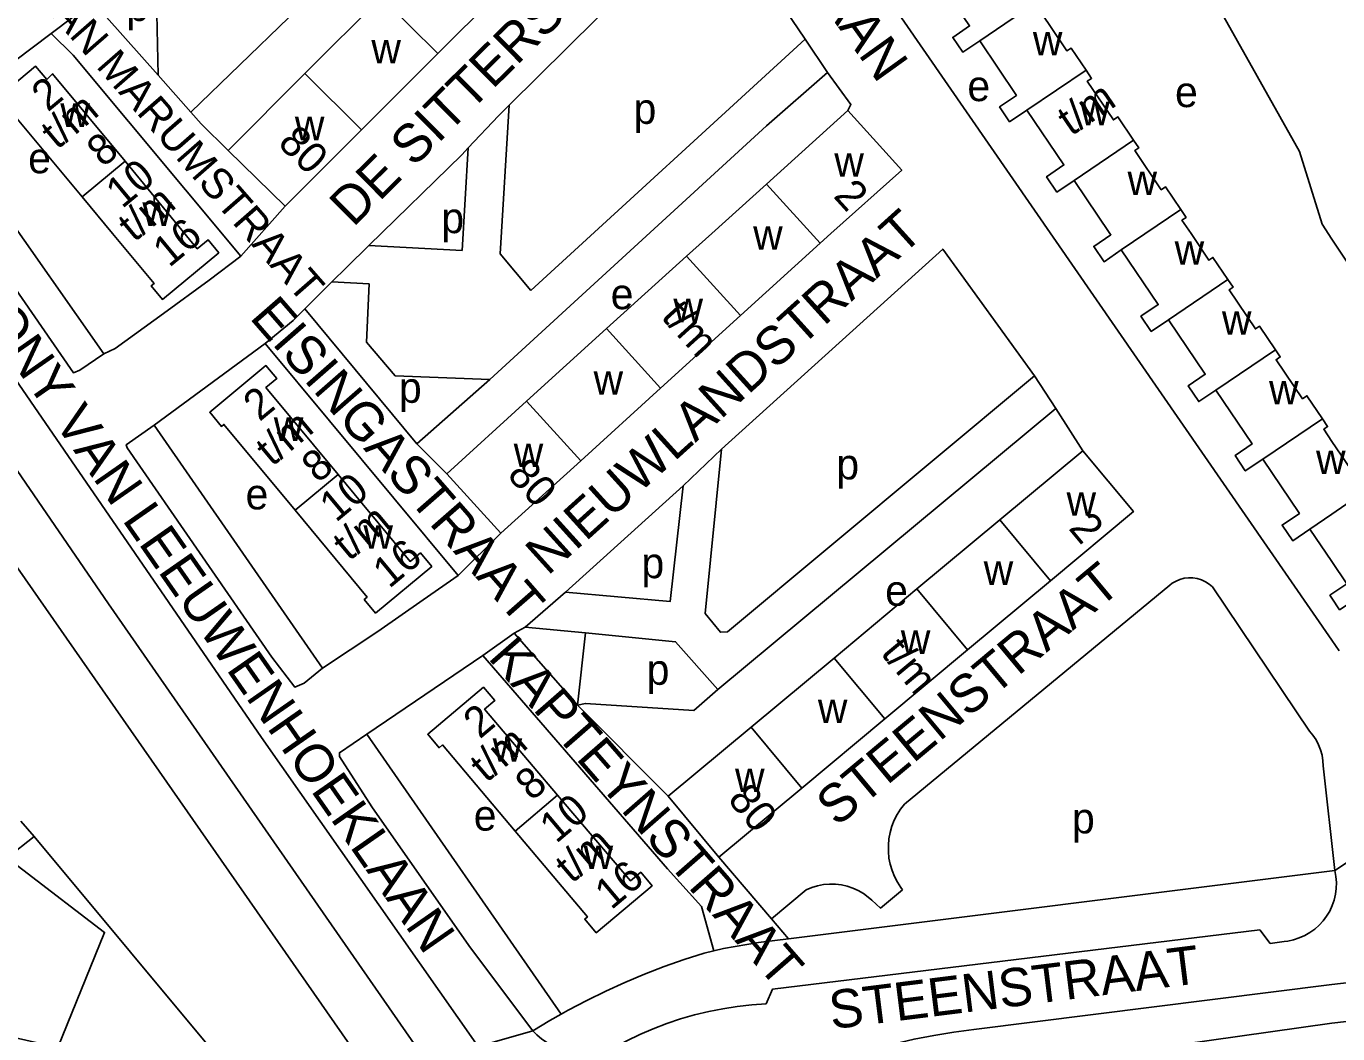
# Model space of a CAD drawing. Extents: x 159902 to 161769, y 383692 to 384875.
# Drawn here: x 160329.3 to 160500.8, y 384145.4 to 384277.1 of the extents above; entities that cross this region are included whole.
import ezdxf

# ---------------------------------------------------------------- set-up
doc = ezdxf.new("R2010")
doc.units = 0
for name, color, linetype in [('BLT_Basislijn', 7, 'Continuous'), ('BLT_Bebouwing', 7, 'Continuous'), ('BLT_Centroide', 7, 'Continuous'), ('BLT_Huisnummer_reeks', 7, 'Continuous'), ('BLT_Onderverdeling_panden', 7, 'Continuous'), ('BLT_Straatnaam', 7, 'Continuous'), ('BLT_Straatnaam_verkleind', 7, 'Continuous'), ('BLT_Vlakafsluiter', 7, 'Continuous')]:
    doc.layers.add(name, color=color, linetype=linetype)

msp = doc.modelspace()

# ---------------------------------------------------------------- linework, layer by layer
at = {"layer": 'BLT_Basislijn'}
for p, q in [((160337.69, 384280.72), (160346.57, 384270.7)), ((160340.11, 384201.6), (160288.34, 384276.94)), ((160347.99, 384201.77), (160297.57, 384275.01)), ((160332.58, 384276.15), (160317.87, 384265.05)), ((160395.28, 384242.55), (160431.13, 384275.39)), ((160431.13, 384275.39), (160434.06, 384271.04)), ((160346.57, 384270.7), (160350.87, 384265.85)), ((160392.46, 384266.78), (160391.29, 384247.35)), ((160317.87, 384265.05), (160339.47, 384234.3)), ((160350.87, 384265.85), (160352.22, 384264.33)), ((160391.07, 384265.4), (160387.12, 384261.18)), ((160352.22, 384264.33), (160355.75, 384260.84)), ((160387.12, 384261.18), (160386.28, 384260.28)), ((160387.12, 384261.18), (160386.3, 384247.76)), ((160374.12, 384248.43), (160386.28, 384260.28)), ((160357.37, 384247.06), (160363.19, 384253.56)), ((160371.24, 384245.61), (160374.12, 384248.43)), ((160374.12, 384248.43), (160386.3, 384247.76)), ((160391.29, 384247.35), (160395.28, 384242.55)), ((160371.24, 384245.61), (160369.3, 384243.69)), ((160369.3, 384243.69), (160365.74, 384240.14)), ((160369.3, 384243.69), (160374.18, 384243.42)), ((160365.74, 384240.14), (160364.24, 384238.65)), ((160365.74, 384240.14), (160380.38, 384222.53)), ((160360.58, 384235.63), (160364.24, 384238.65)), ((160346.07, 384224.95), (160360.58, 384235.63)), ((160360.58, 384235.63), (160385.81, 384205.33)), ((160461.11, 384231.42), (160463.92, 384227.15)), ((160419.74, 384190.41), (160463.92, 384227.15)), ((160467.42, 384221.62), (160463.92, 384227.15)), ((160346.07, 384224.95), (160368.07, 384193.18)), ((160380.38, 384222.53), (160384.31, 384218.61)), ((160415.21, 384217.03), (160420.23, 384221.83)), ((160399.82, 384203.14), (160415.21, 384217.03)), ((160325.46, 384210.23), (160383.08, 384127.6)), ((160385.81, 384205.33), (160391.37, 384210.83)), ((160394.54, 384198.54), (160399.82, 384203.14)), ((160478.82, 384204.05), (160444.15, 384175.44)), ((160484.38, 384203.81), (160497.05, 384184.98)), ((160384.44, 384137.82), (160340.11, 384201.6)), ((160393.13, 384197.76), (160389, 384194.87)), ((160394.54, 384198.54), (160393.13, 384197.76)), ((160401.38, 384188.38), (160393.13, 384197.76)), ((160394.54, 384198.54), (160402.45, 384197.8)), ((160401.38, 384188.38), (160402.45, 384197.8)), ((160373.86, 384184.59), (160389, 384194.87)), ((160413.16, 384166.98), (160389, 384194.87)), ((160401.38, 384188.38), (160413.26, 384176.46)), ((160373.86, 384184.59), (160399.27, 384147.98)), ((160498.85, 384180.42), (160500.37, 384166.74)), ((160328.65, 384173.22), (160330.39, 384171.22)), ((160419.88, 384168.51), (160426.74, 384160.44)), ((160428.96, 384157.83), (160500.37, 384166.74)), ((160431.3, 384164.25), (160426.74, 384160.44)), ((160426.74, 384160.44), (160428.96, 384157.83)), ((160387.2, 384156.98), (160393.43, 384148.64)), ((160425.03, 384157.34), (160428.96, 384157.83)), ((160419.21, 384156.26), (160417.95, 384155.97)), ((160395.57, 384145.81), (160393.43, 384148.64))]:
    msp.add_line(p, q, dxfattribs=at)
for points in [[(160437.92, 384298.9), (160433.19, 384295.39), (160432.67, 384294.41), (160432.8, 384294.03), (160500, 384196.88), (160500.95, 384195.48)], [(160474.04, 384299.43), (160495.78, 384260.7), (160498.73, 384251.22), (160500, 384249.27), (160516.04, 384225.27), (160524.9, 384211.57)], [(160392.46, 384266.78), (160419.14, 384293.17), (160431.13, 384275.39)], [(160341.22, 384284.55), (160346.29, 384284.78), (160346.57, 384270.7)], [(160371.44, 384283.91), (160363.52, 384283.56), (160363.67, 384278.22), (160350.87, 384265.85)], [(160336.71, 384279.66), (160335.43, 384278.29), (160332.58, 384276.15)], [(160332.58, 384276.15), (160335.47, 384273.29), (160357.37, 384247.06)], [(160389.95, 384230.91), (160426.08, 384264.06), (160434.06, 384271.04)], [(160436.74, 384266.06), (160437.13, 384266.84), (160434.06, 384271.04)], [(160391.07, 384265.4), (160392.46, 384266.78)], [(160317.87, 384265.05), (160315.2, 384263.24), (160314.49, 384262.19), (160335.53, 384231.79), (160336.36, 384232.14), (160339.47, 384234.3)], [(160420.23, 384221.83), (160449.14, 384247.96), (160461.11, 384231.42)], [(160339.47, 384234.3), (160340.98, 384234.97), (160347.26, 384239.54), (160353.25, 384243.92), (160357.37, 384247.06)], [(160374.18, 384243.42), (160373.8, 384235.82), (160377.55, 384231.42), (160389.95, 384230.91)], [(160380.38, 384222.53), (160389.95, 384230.91)], [(160420.23, 384221.83), (160418.09, 384200.36), (160420.08, 384197.9), (160421, 384197.93), (160461.11, 384231.42)], [(160346.07, 384224.95), (160342.38, 384222.38), (160342.55, 384222.01), (160361.42, 384194.64), (160364.45, 384190.7), (160365.65, 384191.22), (160368.07, 384193.18)], [(160415.21, 384217.03), (160413.52, 384201.92), (160399.82, 384203.14)], [(160368.07, 384193.18), (160375.28, 384198.01), (160381.23, 384202.12), (160385.81, 384205.33)], [(160484.38, 384203.81), (160483.95, 384204.18), (160483.47, 384204.5), (160482.95, 384204.74), (160482.4, 384204.91), (160481.84, 384205), (160481.27, 384205.02), (160480.7, 384204.95), (160480.14, 384204.8), (160479.62, 384204.58), (160479.12, 384204.29), (160478.82, 384204.05)], [(160388.43, 384143.74), (160360.11, 384184.15), (160347.99, 384201.77)], [(160419.74, 384190.41), (160414.21, 384196.65), (160402.45, 384197.8)], [(160419.74, 384190.41), (160416.6, 384187.69), (160402.43, 384188.6), (160401.38, 384188.38)], [(160373.86, 384184.59), (160370.27, 384182.15), (160370.3, 384181.66), (160374.53, 384175.09), (160387.2, 384156.98)], [(160497.05, 384184.98), (160497.52, 384184.43), (160497.93, 384183.83), (160498.26, 384183.19), (160498.52, 384182.52), (160498.71, 384181.82), (160498.82, 384181.1), (160498.85, 384180.42)], [(160444.15, 384175.44), (160443.63, 384174.78), (160443.18, 384174.07), (160442.8, 384173.32), (160442.49, 384172.54), (160442.25, 384171.73), (160442.1, 384170.91), (160442.02, 384170.07), (160442.02, 384169.23), (160442.1, 384168.39), (160442.27, 384167.57), (160442.51, 384166.76), (160442.82, 384165.98), (160443.21, 384165.23), (160443.66, 384164.53), (160443.87, 384164.25)], [(160276.65, 384143.51), (160311.94, 384100.91), (160323.37, 384087.49), (160323.99, 384087.44), (160338.85, 384099.46), (160367.31, 384123.31), (160368.68, 384124.84), (160368.13, 384125.84), (160330.39, 384171.22)], [(160330.39, 384171.22), (160326.86, 384168.4), (160328.88, 384166.85)], [(160413.16, 384166.98), (160417.6, 384162.05), (160419.21, 384156.26)], [(160313.28, 384152.52), (160317.83, 384147.19), (160333.48, 384143.65), (160339.59, 384158.66), (160328.88, 384166.85)], [(160500.37, 384166.74), (160500.51, 384165.97), (160500.58, 384165.2), (160500.56, 384164.43), (160500.46, 384163.66), (160500.29, 384162.9), (160500.04, 384162.17), (160499.71, 384161.46), (160499.31, 384160.8), (160498.85, 384160.17), (160498.33, 384159.6), (160497.75, 384159.09), (160497.12, 384158.64), (160496.44, 384158.25), (160495.73, 384157.94), (160494.99, 384157.7), (160494.23, 384157.54), (160493.74, 384157.48)], [(160431.3, 384164.25), (160432.02, 384164.55), (160432.77, 384164.77), (160433.54, 384164.92), (160434.32, 384164.98), (160435.1, 384164.97), (160435.88, 384164.88), (160436.64, 384164.71), (160437.38, 384164.46), (160438.09, 384164.14), (160438.77, 384163.74), (160439.4, 384163.28), (160439.87, 384162.87)], [(160439.87, 384162.87), (160440.99, 384161.84), (160443.87, 384164.25)], [(160493.74, 384157.48), (160491.94, 384157.2), (160490.56, 384159), (160426.88, 384151.26), (160426.05, 384149.32)], [(160425.03, 384157.34), (160420.47, 384156.55), (160419.21, 384156.26)], [(160417.95, 384155.97), (160415.32, 384155.13), (160412.72, 384154.21), (160410.15, 384153.21), (160407.6, 384152.14), (160405.09, 384151), (160402.61, 384149.78), (160400.17, 384148.49), (160399.27, 384147.98)], [(160527.99, 384155.07), (160500, 384151.86), (160453.18, 384146)], [(160426.05, 384149.32), (160424.16, 384149.19), (160422.27, 384148.99), (160420.4, 384148.7), (160418.54, 384148.33), (160416.7, 384147.88), (160414.87, 384147.36), (160413.07, 384146.76), (160411.3, 384146.09), (160409.56, 384145.34), (160407.85, 384144.52), (160406.18, 384143.63), (160405.74, 384143.38)], [(160513.4, 384148.33), (160500, 384146.79), (160468.24, 384142.34), (160453.61, 384138.94), (160446.91, 384136.68), (160439.69, 384133.26), (160431.46, 384128.18), (160423.21, 384121.53)], [(160399.27, 384147.98), (160397.77, 384147.14), (160395.57, 384145.81)], [(160405.74, 384143.38), (160404.92, 384143.11), (160404.08, 384142.92), (160403.22, 384142.81), (160402.36, 384142.78), (160401.5, 384142.83), (160400.64, 384142.95), (160399.8, 384143.16), (160398.99, 384143.44), (160398.2, 384143.8), (160397.45, 384144.23), (160396.74, 384144.72), (160396.09, 384145.28), (160395.57, 384145.81)], [(160453.18, 384146), (160450.58, 384145.65), (160447.98, 384145.22), (160445.39, 384144.72), (160442.83, 384144.13), (160440.28, 384143.47), (160437.75, 384142.73), (160435.24, 384141.91), (160432.77, 384141.02), (160430.32, 384140.05), (160427.9, 384139.01), (160425.51, 384137.9), (160423.16, 384136.71), (160420.85, 384135.46), (160418.57, 384134.13), (160416.34, 384132.74), (160414.94, 384131.8)]]:
    msp.add_lwpolyline(points, dxfattribs=at)
at = {"layer": 'BLT_Bebouwing'}
for p, q in [((160393.08, 384283.49), (160383.12, 384273.51)), ((160365.77, 384270.9), (160375.73, 384280.89)), ((160383.12, 384273.51), (160373.15, 384263.54)), ((160355.75, 384260.84), (160365.77, 384270.9)), ((160426.11, 384256.47), (160436.74, 384266.06)), ((160373.15, 384263.54), (160363.19, 384253.56)), ((160363.19, 384253.56), (160355.75, 384260.84)), ((160433.12, 384248.75), (160422.69, 384239.27)), ((160405.18, 384237.57), (160415.62, 384247.05)), ((160422.69, 384239.27), (160412.25, 384229.79)), ((160394.74, 384228.09), (160405.18, 384237.57)), ((160412.25, 384229.79), (160401.81, 384220.31)), ((160384.31, 384218.61), (160394.74, 384228.09)), ((160401.81, 384220.31), (160391.37, 384210.83)), ((160456.58, 384212.58), (160467.42, 384221.62)), ((160391.37, 384210.83), (160384.31, 384218.61)), ((160445.75, 384203.55), (160456.58, 384212.58)), ((160463.2, 384204.63), (160452.37, 384195.6)), ((160434.92, 384194.52), (160445.75, 384203.55)), ((160424.09, 384185.49), (160434.92, 384194.52)), ((160452.37, 384195.6), (160441.54, 384186.57)), ((160441.54, 384186.57), (160430.71, 384177.54)), ((160413.26, 384176.46), (160424.09, 384185.49)), ((160430.71, 384177.54), (160419.88, 384168.51)), ((160419.88, 384168.51), (160413.26, 384176.46))]:
    msp.add_line(p, q, dxfattribs=at)
for points in [[(160447.79, 384284.29), (160452.63, 384277.12), (160450.43, 384275.63), (160451.76, 384273.68), (160453.96, 384275.17)], [(160461.74, 384280.43), (160462.42, 384279.43), (160461.86, 384279.05), (160465.36, 384273.86), (160465.91, 384274.24), (160467.86, 384271.35)], [(160453.96, 384275.17), (160458.77, 384268.05), (160456.55, 384266.55), (160457.87, 384264.6), (160460.12, 384266.12)], [(160336.63, 384254.79), (160327.27, 384266.03), (160326.87, 384265.7), (160325.33, 384267.51), (160330.56, 384271.85), (160332.04, 384270.12), (160332.77, 384270.87), (160342.25, 384259.46)], [(160467.86, 384271.35), (160468.58, 384270.28), (160468.02, 384269.9), (160471.44, 384264.84), (160472.02, 384265.23), (160474.08, 384262.19)], [(160436.74, 384266.06), (160443.77, 384258.3), (160434.5, 384250), (160433.12, 384248.75)], [(160460.12, 384266.12), (160464.96, 384258.96), (160462.7, 384257.43), (160464.06, 384255.42), (160466.3, 384256.93)], [(160474.08, 384262.19), (160474.75, 384261.19), (160474.23, 384260.84), (160477.69, 384255.71), (160478.25, 384256.09), (160480.26, 384253.12)], [(160342.25, 384259.46), (160351.7, 384248.02), (160353.11, 384249.18), (160354.51, 384247.49), (160347.15, 384241.4), (160345.68, 384243.17), (160346.04, 384243.46), (160340.62, 384250), (160336.63, 384254.79)], [(160415.62, 384247.05), (160418.94, 384250), (160426.11, 384256.47)], [(160466.3, 384256.93), (160470.99, 384250), (160471.11, 384249.83), (160468.87, 384248.31), (160470.22, 384246.32), (160472.47, 384247.85)], [(160480.26, 384253.12), (160480.94, 384252.11), (160480.4, 384251.74), (160481.58, 384250.01), (160483.91, 384246.51), (160484.44, 384246.87), (160486.39, 384243.98)], [(160472.47, 384247.85), (160477.29, 384240.72), (160475.03, 384239.19), (160476.38, 384237.2), (160478.63, 384238.73)], [(160486.39, 384243.98), (160487.07, 384242.98), (160486.56, 384242.63), (160490, 384237.54), (160490.53, 384237.9), (160492.62, 384234.81)], [(160478.63, 384238.73), (160483.45, 384231.6), (160481.2, 384230.09), (160482.6, 384228.03), (160484.82, 384229.53)], [(160492.62, 384234.81), (160493.25, 384233.87), (160492.71, 384233.51), (160496.16, 384228.41), (160496.72, 384228.79), (160498.75, 384225.79)], [(160364.48, 384213.84), (160355.17, 384225.05), (160354.85, 384224.79), (160353.32, 384226.64), (160360.67, 384232.74), (160362.08, 384231.04), (160360.66, 384229.86), (160370.09, 384218.5)], [(160484.82, 384229.53), (160489.57, 384222.5), (160487.33, 384220.98), (160488.68, 384218.98), (160490.95, 384220.51)], [(160498.75, 384225.79), (160499.44, 384224.77), (160498.93, 384224.42), (160500, 384222.84), (160502.42, 384219.25), (160502.95, 384219.61), (160504.91, 384216.71)], [(160467.42, 384221.62), (160474.05, 384213.67), (160463.2, 384204.63)], [(160490.95, 384220.51), (160495.74, 384213.43), (160493.49, 384211.91), (160494.88, 384209.86), (160497.12, 384211.37)], [(160370.09, 384218.5), (160379.52, 384207.15), (160380.87, 384208.26), (160382.34, 384206.49), (160375, 384200.4), (160373.52, 384202.17), (160373.9, 384202.49), (160364.48, 384213.84)], [(160497.12, 384211.37), (160499.99, 384207.12), (160501.96, 384204.23), (160500, 384202.91), (160499.74, 384202.73), (160500, 384202.35), (160501, 384200.84), (160503.25, 384202.3)], [(160393.24, 384171.9), (160383.74, 384183.18), (160383.29, 384182.8), (160381.81, 384184.56), (160389.1, 384190.7), (160390.57, 384188.96), (160389.25, 384187.84), (160398.79, 384176.62)], [(160398.79, 384176.62), (160408.33, 384165.4), (160409.67, 384166.53), (160411.15, 384164.77), (160403.85, 384158.62), (160402.34, 384160.41), (160402.68, 384160.7), (160393.24, 384171.9)]]:
    msp.add_lwpolyline(points, dxfattribs=at)
at = {"layer": 'BLT_Onderverdeling_panden'}
for p, q in [((160375.73, 384280.89), (160383.12, 384273.51)), ((160453.96, 384275.17), (160461.74, 384280.43)), ((160365.77, 384270.9), (160373.15, 384263.54)), ((160460.12, 384266.12), (160467.86, 384271.35)), ((160466.3, 384256.93), (160474.08, 384262.19)), ((160342.25, 384259.46), (160336.63, 384254.79)), ((160426.11, 384256.47), (160433.12, 384248.75)), ((160472.47, 384247.85), (160480.26, 384253.12)), ((160415.62, 384247.05), (160422.69, 384239.27)), ((160478.63, 384238.73), (160486.39, 384243.98)), ((160405.18, 384237.57), (160412.25, 384229.79)), ((160484.82, 384229.53), (160492.62, 384234.81)), ((160394.74, 384228.09), (160401.81, 384220.31)), ((160490.95, 384220.51), (160498.75, 384225.79)), ((160370.09, 384218.5), (160364.48, 384213.84)), ((160456.58, 384212.58), (160463.2, 384204.63)), ((160445.75, 384203.55), (160452.37, 384195.6)), ((160434.92, 384194.52), (160441.54, 384186.57)), ((160424.09, 384185.49), (160430.71, 384177.54)), ((160398.79, 384176.62), (160393.24, 384171.9))]:
    msp.add_line(p, q, dxfattribs=at)
msp.add_lwpolyline([(160497.12, 384211.37), (160500, 384213.32), (160504.91, 384216.71)], dxfattribs=at)
at = {"layer": 'BLT_Vlakafsluiter'}
for p, q in [((160500.37, 384166.74), (160510.3, 384173.37)), ((160388.43, 384143.74), (160395.57, 384145.81))]:
    msp.add_line(p, q, dxfattribs=at)

# ---------------------------------------------------------------- texts
at = {"layer": 'BLT_Centroide'}
for s, p in [('p', (160342.42, 384277.78)), ('w', (160374.45, 384272.22)), ('w', (160460.91, 384273.27)), ('e', (160452.35, 384267.3)), ('e', (160479.49, 384266.52)), ('w', (160333.8, 384263.92)), ('p', (160408.72, 384264.33)), ('w', (160467.09, 384264.16)), ('w', (160364.45, 384262.19)), ('e', (160329.59, 384257.87)), ('w', (160434.96, 384257.41)), ('w', (160473.28, 384255.03)), ('w', (160344.52, 384251)), ('p', (160383.59, 384250.05)), ('w', (160424.35, 384247.88)), ('w', (160479.44, 384245.92)), ('e', (160405.73, 384240.11)), ('w', (160413.93, 384238.41)), ('w', (160485.62, 384236.77)), ('w', (160403.49, 384228.94)), ('p', (160378.05, 384227.88)), ('w', (160491.78, 384227.66)), ('w', (160361.7, 384222.89)), ('w', (160393.05, 384219.47)), ('p', (160435.22, 384217.87)), ('w', (160497.92, 384218.56)), ('e', (160358.01, 384213.95)), ('w', (160465.31, 384213.12)), ('w', (160373.41, 384208.8)), ('p', (160409.75, 384204.96)), ('w', (160454.48, 384204.09)), ('e', (160441.61, 384201.35)), ('w', (160443.65, 384195.06)), ('p', (160410.43, 384191.03)), ('w', (160432.81, 384186.03)), ('w', (160390.3, 384180.98)), ('w', (160421.98, 384177)), ('e', (160387.83, 384171.97)), ('p', (160466.02, 384171.61)), ('w', (160402.19, 384166.95))]:
    msp.add_text(s, height=4, dxfattribs=at).set_placement(p)
at = {"layer": 'BLT_Huisnummer_reeks'}
for s, rotation, p in [('2', 39.7075, (160332.16, 384265.8)), ('t/m', 34.073, (160465.9, 384262.66)), ('t/m', 39.697, (160333.38, 384260.87)), ('8', 39.697, (160339.38, 384258.55)), ('80', 315.6184, (160362.08, 384261.64)), ('10', 39.697, (160341.87, 384253.16)), ('2', 312.2513, (160434.72, 384254.83)), ('t/m', 39.697, (160343.45, 384248.77)), ('16', 39.7102, (160348.02, 384245.46)), ('t/m', 312.255, (160412.19, 384239.05)), ('2', 39.7075, (160359.83, 384225.34)), ('t/m', 39.697, (160361.46, 384219.46)), ('8', 39.697, (160367.46, 384217.28)), ('80', 312.2473, (160392.06, 384218.36)), ('10', 39.697, (160369.81, 384212.16)), ('t/m', 39.697, (160371.53, 384207.1)), ('2', 309.8141, (160465.47, 384211.44)), ('16', 39.7102, (160376.77, 384203.52)), ('t/m', 309.8183, (160440.91, 384195.13)), ('2', 40.1227, (160388.62, 384183.86)), ('t/m', 40.3735, (160389.49, 384178.13)), ('8', 40.1277, (160395.4, 384175.74)), ('80', 309.8183, (160420.9, 384175.99)), ('10', 40.1277, (160398.6, 384170.2)), ('t/m', 40.3735, (160400.64, 384164.96)), ('16', 40.1277, (160405.8, 384161.52))]:
    msp.add_text(s, height=4, rotation=rotation, dxfattribs=at).set_placement(p)
at = {"layer": 'BLT_Straatnaam'}
for s, rotation, p in [('METIUSLAAN', 305.609, (160415.93, 384304.21)), ('DE SITTERSTRAAT', 44.6923, (160372.06, 384250.72)), ('NIEUWLANDSTRAAT', 42.1113, (160397.5, 384205.19)), ('ANTONY VAN LEEUWENHOEKLAAN', 304.8833, (160315.88, 384249.75)), ('EISINGASTRAAT', 311.1484, (160358.42, 384238.97)), ('STEENSTRAAT', 39.8172, (160435.29, 384172.36)), ('KAPTEYNSTRAAT', 311.1484, (160389.59, 384194.52)), ('STEENSTRAAT', 7.1359, (160434.6, 384146.01))]:
    msp.add_text(s, height=5, rotation=rotation, dxfattribs=at).set_placement(p)
at = {"layer": 'BLT_Straatnaam_verkleind'}
msp.add_text('VAN MARUMSTRAAT', height=4, rotation=311.1484, dxfattribs=at).set_placement((160330.15, 384281.21))

doc.saveas('drawing.dxf')
